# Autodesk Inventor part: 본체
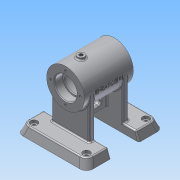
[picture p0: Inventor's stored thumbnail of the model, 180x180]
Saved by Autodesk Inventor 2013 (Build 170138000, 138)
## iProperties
Created: 2016-07
Part Number: 본체
Material: 알루미늄 6061
Document SubType Name: Modeling
Designer: Administrator
Density: 2.71 g/cm^3
Mass: 497.861 g
Surface Area: 538.025 cm^2
Volume: 183.713 cm^3
Author: Administrator
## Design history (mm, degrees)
sketch "스케치1"
  geometry: C1 r 27 at (0, 0); 1 further point
  constraints: 1 centre point, 1 coincident
  dimensions: "d0" = 54 diameter of C1
extrude "돌출1" new body sketch "스케치1" stored distance "d3" = 70; taper "d4" = 0 deg
node "작업 평면1"
sketch "스케치2"
  geometry: L1 (50, -55)-(-50, -55); L2 (-50, -55)-(-50, -20); L3 (-50, -20)-(50, -20); L4 (50, -20)-(50, -55); L5 (50, 20)-(-50, 20); L6 (-50, 20)-(-50, 55); L7 (-50, 55)-(50, 55); L8 (50, 55)-(50, 20); 1 further point
  constraints: 16 end point, 4 parallel, 2 collinear, 2 horizontal, 2 perpendicular
  dimensions: "d8" = 35 distance of L5.end L6.end; "d9" = 35 distance of L1.end L2.end; "d10" = 110 distance between parallel lines of L7 L1; "d11" = 50 distance from line of point (0, 0) L4; "d12" = 100 distance of L1.start L1.end; "d13" = 55 distance from line of point (0, 0) L1
extrude "돌출2" join sketch "스케치2" distance "d14" = 12; taper "d15" = 0 deg
sketch "스케치6"
  geometry: L1 (-48, 20.072)-(-48, -20.313); L2 (-48, -20.313)-(2, -20.313); L3 (2, -20.313)-(2, 20.072); L4 (2, 20.072)-(-48, 20.072); L5 (-27, -35)-(-27, 35) reference; 1 further point
  constraints: 8 end point, 2 parallel, 1 perpendicular, 1 vertical
  dimensions: "d28" = 21 distance between parallel lines of L1 L5; "d29" = 50 distance between parallel lines of L1 L3
extrude "돌출6" join sketch "스케치6" stored distance "d30" = 8; taper "d31" = 0 deg
sketch "스케치14"
  geometry: L1 (23, 70)-(23, 11.296); L2 (77, 70)-(77, 11.296); L3 (23, 11.296)-(77, 11.296); A1 r 27 centre (50, 70) between (77, 70) and (23, 70) reference; 1 further point
  constraints: 6 end point, 2 point on circle, 2 tangent, 1 parallel, 1 perpendicular, 1 vertical
extrude "돌출9" join sketch "스케치14" distance "d165" = 8; taper "d166" = 0 deg
sketch "스케치15"
  geometry: L1 (23, 70)-(23, 12); L2 (23, 12)-(77, 12); L3 (77, 12)-(77, 70); L4 (100, 12)-(0, 12) reference; A1 r 27 centre (50, 70) between (77, 70) and (23, 70) reference; 1 further point
  constraints: 6 end point, 2 point on circle, 2 tangent, 1 collinear, 1 parallel, 1 perpendicular, 1 vertical
extrude "돌출10" join sketch "스케치15" distance "d167" = 8; taper "d168" = 0 deg
feature "면 기울기1" dims angle "d169" = 20 deg
feature "면 기울기2" dims angle "d170" = 20 deg
feature "면 기울기3" dims angle "d171" = 20 deg
feature "면 기울기4" dims angle "d172" = 20 deg
feature "면 기울기5" dims angle "d173" = 20 deg
feature "면 기울기6" dims angle "d174" = 20 deg
fillet "모깎기17" dims "d175" = 10
fillet "모깎기18" dims "d176" = 2
fillet "모깎기19" dims "d177" = 2
fillet "모깎기20" dims "d178" = 2
fillet "모깎기21" dims "d179" = 2
fillet "모깎기22" dims "d180" = 2
fillet "모깎기23" dims "d181" = 2
fillet "모깎기24" dims "d182" = 2
fillet "모깎기25" dims "d183" = 2
fillet "모깎기26" dims "d184" = 2
sketch "스케치8"
  geometry: L1 (0, 35)-(0, -35); L2 (0, 35)-(16, 35); L3 (16, 35)-(16, 23); L4 (16, 23)-(14, 23); L5 (14, 23)-(14, 21); L6 (14, 21)-(22, 21); L7 (22, 21)-(22, -21); L8 (22, -21)-(14, -21); L9 (14, -21)-(14, -23); L10 (14, -23)-(16, -23); L11 (16, -23)-(16, -35); L12 (16, -35)-(0, -35); 2 further points
  constraints: 24 end point, 6 parallel, 5 perpendicular, 1 coincident, 1 midpoint, 1 vertical
  dimensions: "d46" = 70 distance of L1.start L1.end; "d48" = 32 diameter of L3 L1; "d49" = 28 diameter of L5 L1; "d50" = 44 diameter of L7 L1; "d51" = 28 diameter of L9 L1; "d52" = 32 diameter of L11 L1; "d53" = 12 distance of L2.end L3.end; "d54" = 42 distance of L6.end L7.end; "d55" = 12 distance of L10.end L11.end; "d56" = 2 distance of L4.end L5.end
revolve "회전1" sketch "스케치8" stored, may be unused: angle "d57" = 90 deg
fillet "모깎기9" dims "d58" = 0.3
fillet "모깎기10" dims "d59" = 3
chamfer "모따기1" distance "d60" = 1; stored, may be unused: second distance "d61" = 2, angle "d62" = 45 deg
sketch "스케치9"
  geometry: 2 further points
  constraints: 1 vertical alignment
  dimensions: "d63" = 21 distance of point (0, 0) point (0, 21)
hole "구멍1" sketch "스케치9" at (0, 21) diameter "d64" = 3.242; stored, may be unused: countersink angle "d68" = 90 deg, drill point angle "d70" = 118 deg; dims "d65" = 8, "d66" = 4, "d67" = 2, "d69" = 10
node "작업 평면2"
sketch "스케치10"
  geometry: L1 (27, 35)-(-27, 35) reference; C1 r 5 at (0, 13); 2 further points
  constraints: 1 centre point, 1 midpoint, 1 vertical alignment
  dimensions: "d76" = 22 distance from line of L1 C1.centre; "d77" = 10 diameter of C1
extrude "돌출8" join sketch "스케치10" stored distance "d78" = 8; taper "d79" = 0 deg
fillet "모깎기12" dims "d80" = 2
fillet "모깎기14" dims "d82" = 2
hole "구멍2" diameter "d85" = 5.188; stored, may be unused: countersink angle "d89" = 90 deg, drill point angle "d91" = 0 deg; dims "d83" = 10, "d84" = 10, "d86" = 19, "d87" = 4, "d88" = 2, "d90" = 20
sketch "스케치13"
  geometry: L1 (0, 0)-(-11.658, -18.657); L2 (0, 0)-(0, -35.07); L3 (-11.658, -18.657)-(-15.898, -25.441); L4 (-20.986, -22.262)-(-17.515, -16.707); L5 (-20.986, -22.262)-(-15.898, -25.441); L6 (-17.515, -16.707)-(-12.427, -19.887); 1 further point
  constraints: 12 end point, 2 perpendicular, 1 collinear, 1 point on line, 1 vertical, 2 other
  dimensions: "d113" = 32 deg angle of L1 L2; "d114" = 30 distance of L1.start L3.end; "d116" = 12 diameter of L4 L3; "d128" = 6.54998 distance between parallel lines of L5 L6
revolve "회전3" sketch "스케치13" stored, may be unused: angle "d117" = 90 deg
fillet "모깎기16" dims "d118" = 2
hole "구멍9" diameter "d187" = 5.188; stored, may be unused: countersink angle "d191" = 90 deg, drill point angle "d193" = 0 deg; dims "d185" = 10, "d186" = 10, "d188" = 19, "d189" = 10, "d190" = 4, "d192" = 20
sketch "스케치16"
  geometry: L1 (-8, -34.5)-(8, -34.5); L2 (8, -41.5)-(-8, -41.5); L3 (45.603, -70)-(22, -70) reference; A1 r 3.5 centre (8, -38) between (8, -41.5) and (8, -34.5); A2 r 3.5 centre (-8, -38) between (-8, -34.5) and (-8, -41.5); 3 further points
  constraints: 6 point on circle, 4 end point, 4 tangent, 2 centre point, 1 horizontal, 1 horizontal alignment, 1 parallel
  dimensions: "d194" = 3.5 radius of A2; "d196" = 32 distance from line of L3 point (11.5, -38); "d197" = 11.5 horizontal distance of point (0, 0) point (-11.5, -38); "d198" = 23 distance of point (11.5, -38) point (-11.5, -38)
extrude "돌출11" cut sketch "스케치16" stored distance "d199" = 8; taper "d200" = 0 deg
node "작업 평면4"
sketch "스케치17"
  geometry: L1 (27, 35)-(-27, 35) reference; L2 (27, -35)-(27, 35) reference; 2 further points
  constraints: 1 other
  dimensions: "d201" = 35 distance from line of L1 point (0, 0); "d202" = 27 distance from line of point (0, 0) L2
feature "엠보싱2" sketch "스케치17" dims "d28" = 21, "d29" = 50, "d203" = 0.5, "d204" = 0
sketch "스케치18"
  geometry: L1 (-50, -45.603)-(-50, -22) reference; L2 (40.603, -55)-(-40.603, -55) reference; 5 further points
  constraints: 2 horizontal alignment, 2 vertical alignment
  dimensions: "d205" = 85 distance of point (-37.5, -42.5) point (-37.5, 42.5); "d207" = 75 distance of point (37.5, -42.5) point (-37.5, -42.5); "d208" = 12.5 distance from line of L1 point (-37.5, -42.5); "d209" = 12.5 distance from line of L2 point (-37.5, -42.5)
hole "구멍10" sketch "스케치18" at (-37.5, -42.5), (37.5, -42.5), (37.5, 42.5), (-37.5, 42.5) diameter "d210" = 6; stored, may be unused: countersink angle "d214" = 90 deg, drill point angle "d216" = 0 deg; dims "d211" = 19, "d212" = 10, "d213" = 4, "d215" = 20
fillet "모깎기27" dims "d217" = 2
fillet "모깎기28" dims "d218" = 2
node "솔리드1"
pattern_circular "원형 패턴1" dims angle "d72" = 360 deg
mirror "대칭4"
